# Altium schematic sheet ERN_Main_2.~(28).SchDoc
size A; SheetNumber: 2; SheetTotal: 3; SPICEModelCacheYVUKJMZF: <root> / <DocumentId>YVUKJMZF</DocumentId> / <CacheFrame Number="0"> / <Model Name="1n5400" Kind="MDL"> / <Text>*1N5400 MCE / * 50V 3A Si Rectifier pkg:DO-201 1,2 / .MODEL 1N5400 D(IS=2.68E-12 RS=0.00977 N=1.17 TT=1.44E-5 CJO=1.24E-10 / + VJ=0.6 M=0.333 BV=66.6 IBV=1E-5 )</Text> / </Model> / <Model Name="led2" Kind="MDL"> / <Text>*Typ RED,GREEN,YELLOW,AMBER GaAs LED: Vf=2.1V Vr=4V If=40mA trr=3uS / *LED Pinout: 1=A, 2=K / .MODEL LED2 D (IS=93.1P RS=42M N=4.61 BV=4 IBV=10U / + CJO=2.97P VJ=.75 M=.333 TT=4.32U)</Text> / </Model> / </CacheFrame> / </root>
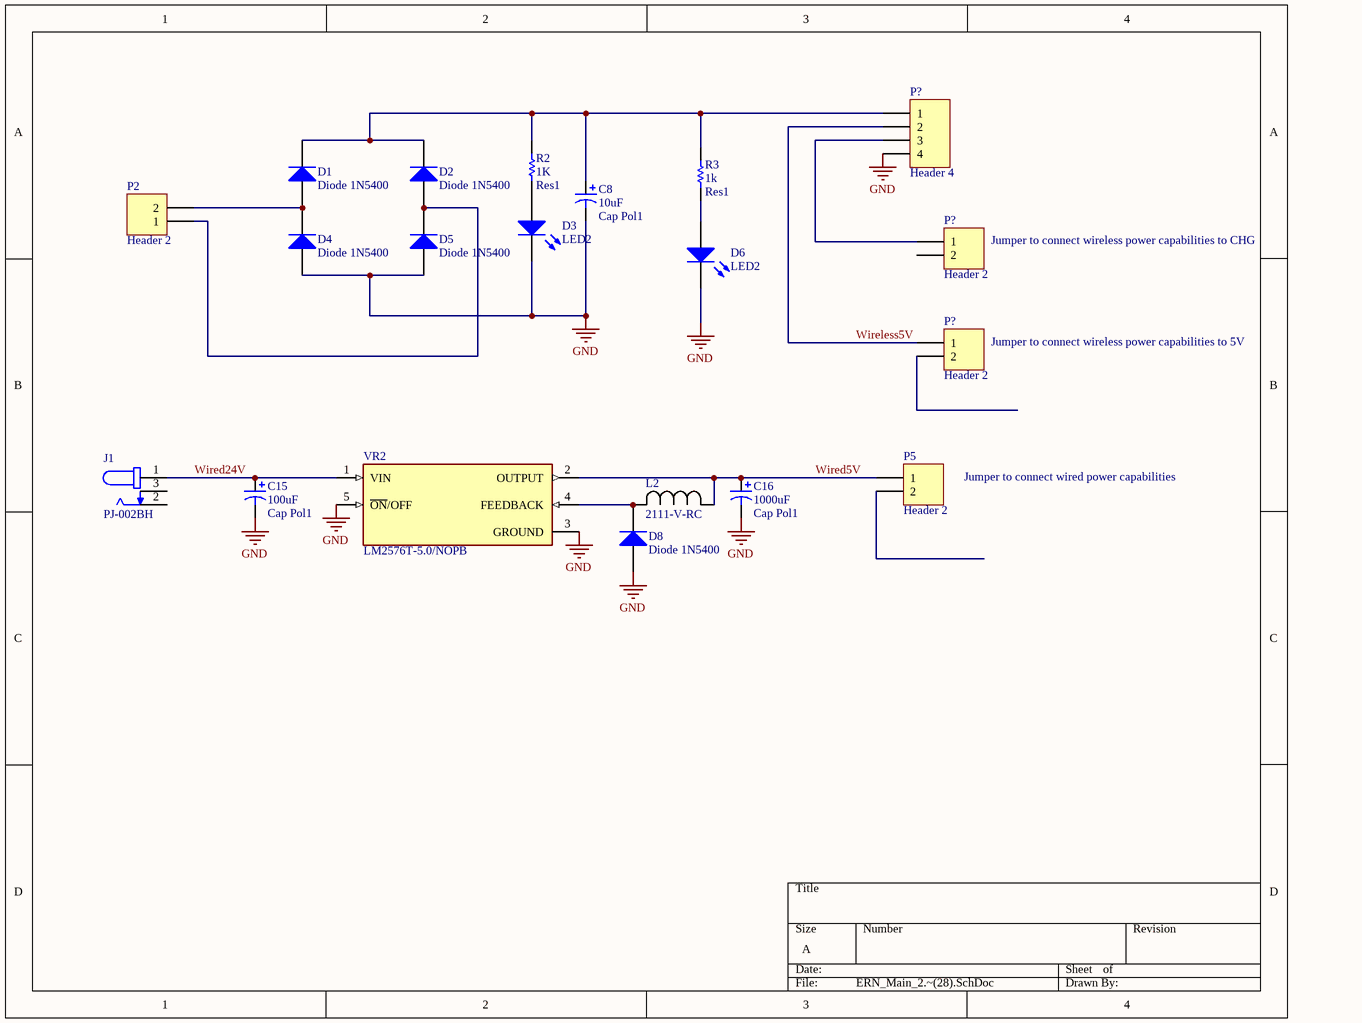
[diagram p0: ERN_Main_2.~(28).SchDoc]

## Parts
(Parts that share a designator on the sheet are numbered #1, #2 ... from top to bottom, then left to right.)
C8  Cap Pol1  value 10uF  [RB7.6-15]
C15  Cap Pol1  value 100uF  [RB7.6-15]
C16  Cap Pol1  value 1000uF  [RB7.6-15]
D1  Diode 1N5400  [DO-201AD]
D2  Diode 1N5400  [DO-201AD]
D3  LED2  [3.2X1.6X1.1]
D4  Diode 1N5400  [DO-201AD]
D5  Diode 1N5400  [DO-201AD]
D6  LED2  [3.2X1.6X1.1]
D8  Diode 1N5400  [DO-201AD]
J1  PJ-002BH  [CUI_PJ-002BH]
L2  2111-V-RC  [IND_21XX_27A_V]
P2  Header 2  [HDR1X2]
P5  Header 2  [HDR1X2]
P?#1  Header 4  [HDR1X4]
P?#2  Header 2  [HDR1X2]
P?#3  Header 2  [HDR1X2]
R2  Res1  value 1K  [AXIAL-0.3]
R3  Res1  value 1k  [AXIAL-0.3]
VR2  LM2576T-5.0/NOPB  [TO170P1067X483X1651-5]

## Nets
GND: C8.2 C15.2 C16.2 D3.2(K) D4.1(A) D5.1(A) D6.2(K) D8.1(A) P?#1.4 VR2.3(GROUND) VR2.5(~{ON}/OFF)
Wired5V: C16.1 L2.1 P5.1 VR2.2(OUTPUT)
Wired24V: C15.1 J1.1 VR2.1(VIN)
Wireless5V: P?#1.2 P?#3.1
NetC8_1: C8.1 D1.2(K) D2.2(K) P?#1.1 R2.2 R3.2
NetD1_1: D1.1(A) D4.2(K) P2.2
NetD2_1: D2.1(A) D5.2(K) P2.1
NetD3_1: D3.1(A) R2.1
NetD6_1: D6.1(A) R3.1
NetD8_2: D8.2(K) L2.2 VR2.4(FEEDBACK)
NetP?#1_3: P?#1.3 P?#2.1

Not connected (* = marked no-connect by the designer): J1 2 3; P5 2; P?#2 2; P?#3 2

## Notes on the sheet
- (near P?#2) Jumper to connect wireless power capabilities to CHG
- (near P?#3) Jumper to connect wireless power capabilities to 5V
- Jumper to connect wired power capabilities

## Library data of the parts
C8 C15 C16 = Cap Pol1: Polarized Capacitor (Radial)
D1 D2 D4 D5 D8 = Diode 1N5400: 3 Amp General Purpose Rectifier
D3 D6 = LED2: Typical RED, GREEN, YELLOW, AMBER GaAs LED
J1 = PJ-002BH: 2.5 x 6.5 mm, 5.0 A, Horizontal, Through Hole, Dc Power Jack Connector; MF: Same Sky
L2 = 2111-V-RC: Inductor 68uH; Manufacturer_Name: Bourns Electronics
P2 P5 P?#2 P?#3 = Header 2: Header, 2-Pin
P?#1 = Header 4: Header, 4-Pin
R2 R3 = Res1: Resistor
VR2 = LM2576T-5.0/NOPB: SIMPLE SWITCHERÂ® 40V, 3A Low Component Count Step-Down Regulator; MF: Texas Instruments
